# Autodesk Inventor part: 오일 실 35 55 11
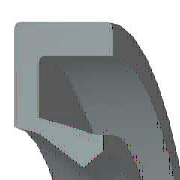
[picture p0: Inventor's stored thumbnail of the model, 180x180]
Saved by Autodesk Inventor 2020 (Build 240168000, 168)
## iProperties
Created: 2012-02
Part Number: 오일 실 35 55 11
Material: 고무
Description: 오일 실 - 비스프링, 조립 GA
Document SubType Name: Modeling
Standard: JIS B 2402
Designer: mdu-01
Standards Organization: JIS
Language: ko-KR
Size Designation: 35 55 11 A
Categories: <MemberInstance><Categories><Category DisplayName="샤프트 부품" InternalName="7f7aeb1f-a693-4053-b835-cee3144e0d98" Mnemonic="SHFT"><Category DisplayName="실링" Intern
Density: 0.93 g/cm^3
Appearance: Rubber-Black
Mass: 8.95413 g
Surface Area: 69.7587 cm^2
Volume: 9.6281 cm^3
IsCustomPart: 1
Author: mdu-01
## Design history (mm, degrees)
body "Solid1"
revolve "회전1" stored, may be unused: angle "d27" = 360 deg
fillet "모깎기1" dims "d28" = 0.55 (= 0.05 x b)
sketch "스케치2"
  geometry: L1 (20.786, -8.25)-(21.786, -11); L2 (19.452, -7.563)-(20.786, -8.25); L3 (17.5, -3.025)-(19.452, -7.563); L4 (19.038, -1.65)-(17.5, -3.025); L5 (23.5, -9.625)-(19.038, -1.65); L6 (23.5, -0.55)-(23.5, -9.625); L7 (25.5, -0.55)-(23.5, -0.55); L8 (25.5, 0)-(25.5, -0.55); L9 (27.5, 0)-(25.5, 0); L10 (27.5, -11)-(27.5, 0); L11 (21.786, -11)-(27.5, -11); L12 (0, -9.6)-(0, 1.6) reference; L13 (28, 0)-(14, 0) reference
  constraints: 22 end point, 3 horizontal, 3 vertical
  dimensions: "d2" = 11 distance of L10.start L9.start (= b); "d4" = 2 distance of L9.start L8.start (= 0.1 x dd - 0.1 x Diam); "d6" = 0.55 distance of L8.start L7.start (= 0.05 x b); "d8" = 1.53846 horizontal distance of L4.start L3.start (= 0.0769231 x dd - 0.0769231 x Diam); "d10" = 1.375 vertical distance of L5.start L10.start (= 0.125 x b); "d12" = 2 distance of L7.start L6.start (= 0.1 x dd - 0.1 x Diam); "d14" = 1.1 vertical distance of L4.start L6.start (= 0.1 x b); "d16" = 5.71429 distance of L1.end L10.start (= 0.285714 x dd - 0.285714 x Diam); "d18" = 1 horizontal distance of L1.start L1.end (= 0.05 x dd - 0.05 x Diam); "d20" = 1.375 vertical distance of L4.start L3.start (= 0.125 x b); "d22" = 2.75 vertical distance of L1.start L1.end (= 0.25 x b); "d24" = 1.33333 horizontal distance of L2.start L1.start (= 0.0666667 x dd - 0.0666667 x Diam); "d26" = 0.6875 vertical distance of L2.start L1.start (= 0.0625 x b); "d29" = 0 distance between parallel lines of L13 L9; "d30" = 17.5 distance from line of L3.start L12 (= 0.5 x Diam); "d31" = 27.5 distance between parallel lines of L12 L10 (= 0.5 x dd)
other parameters: "dd" = 55 [user parameter; used in 7 equation terms], "Diam" = 35 [user parameter; used in 7 equation terms], "b" = 11 [user parameter; used in 8 equation terms], "d1" = 8 (derived), "d3" = 2 (derived), "d5" = 0.4 (derived), "d7" = 1.53846 (derived), "d9" = 1 (derived), "d11" = 2 (derived), "d13" = 0.8 (derived), "d15" = 5.71429 (derived), "d17" = 1 (derived), "d19" = 1 (derived), "d21" = 2 (derived), "d23" = 1.33333 (derived), "d25" = 0.5 (derived), "d32" = 0
